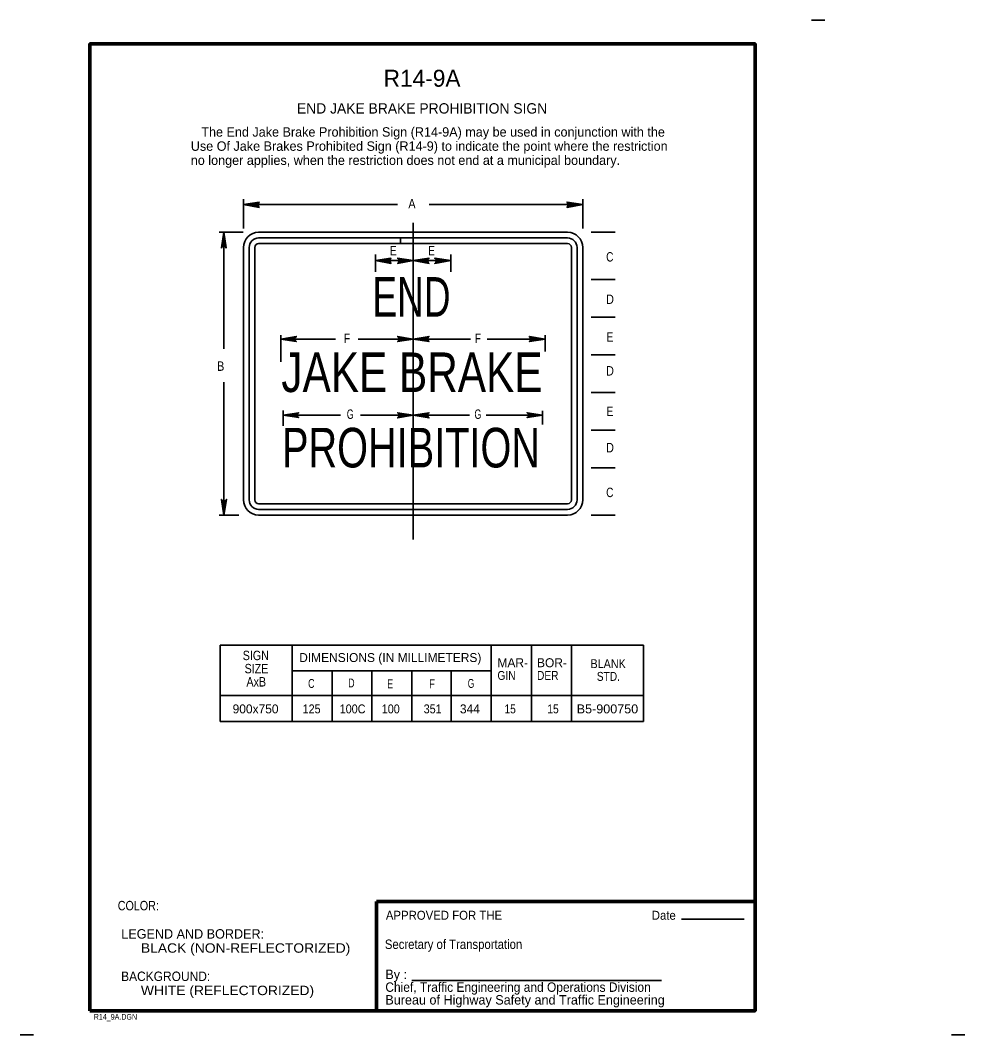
# Model space of a CAD drawing. Extents: x -0.29 to 0.3, y -0.007 to 0.262.
# Drawn here: x -0.2905 to -0.0399, y -0.0074 to 0.2617 of the extents above; entities that cross this region are included whole.
import ezdxf
from ezdxf.enums import TextEntityAlignment as Align

# ---------------------------------------------------------------- set-up
doc = ezdxf.new("R2010")
doc.units = 0
doc.header["$LTSCALE"] = 0.001
doc.linetypes.add('LONG_DASH_SHORT_DASH', pattern=[9.9, 6, -1.2, 1.5, -1.2])
for name, color, linetype, lineweight in [('1', 7, 'Continuous', 35), ('11', 7, 'Continuous', 35), ('12', 7, 'Continuous', 35), ('3', 7, 'Continuous', 35)]:
    doc.layers.add(name, color=color, linetype=linetype, lineweight=lineweight)
doc.layers.add('2', color=7, linetype='Continuous')

msp = doc.modelspace()

# ---------------------------------------------------------------- linework, layer by layer
at = {"layer": '1'}
for p, q in [((-0.077, 0.26175), (-0.0805, 0.26175)), ((-0.115, 0.02325), (-0.098375, 0.02325)), ((-0.186625, 0.007), (-0.120375, 0.007)), ((-0.287, -0.007375), (-0.2905, -0.007375))]:
    msp.add_line(p, q, dxfattribs=at)
at = {"layer": '1', "lineweight": 70}
for q in [(-0.0955, 0.028), (-0.196, -0.001)]:
    msp.add_line((-0.196, 0.028), q, dxfattribs=at)
msp.add_lwpolyline([(-0.272, -0.001), (-0.0955, -0.001), (-0.0955, 0.2555), (-0.272, 0.2555)], close=True, dxfattribs=at)
at = {"layer": '11'}
for p, q in [((-0.22725, 0.2055), (-0.14525, 0.2055)), ((-0.23125, 0.1345), (-0.23125, 0.2015)), ((-0.14125, 0.1345), (-0.14125, 0.2015)), ((-0.14525, 0.1305), (-0.22725, 0.1305))]:
    msp.add_line(p, q, dxfattribs=at)
for centre, start, end in [((-0.22725, 0.2015), 90, 180), ((-0.14525, 0.2015), 0, 90), ((-0.22725, 0.1345), 180, 270), ((-0.14525, 0.1345), 270, 0)]:
    msp.add_arc(centre, 0.004, start, end, dxfattribs=at)
at = {"layer": '12'}
msp.add_line((-0.039875, -0.007375), (-0.043375, -0.007375), dxfattribs=at)
at = {"layer": '3'}
for p, q in [((-0.23125, 0.2065), (-0.23125, 0.21425)), ((-0.190375, 0.212875), (-0.23125, 0.212875)), ((-0.14125, 0.212875), (-0.182, 0.212875)), ((-0.14125, 0.2065), (-0.14125, 0.21425)), ((-0.231375, 0.2055), (-0.23775, 0.2055)), ((-0.2365, 0.174625), (-0.2365, 0.2055)), ((-0.139, 0.2055), (-0.132625, 0.2055)), ((-0.14525, 0.2025), (-0.189625, 0.2025)), ((-0.22975, 0.1345), (-0.22975, 0.2015)), ((-0.22825, 0.2015), (-0.22825, 0.1345)), ((-0.19625, 0.199625), (-0.19625, 0.195)), ((-0.17625, 0.199625), (-0.17625, 0.195)), ((-0.14425, 0.1345), (-0.14425, 0.2015)), ((-0.14275, 0.2015), (-0.14275, 0.1345)), ((-0.18625, 0.198), (-0.19625, 0.198)), ((-0.18625, 0.198), (-0.17625, 0.198)), ((-0.139, 0.193), (-0.132625, 0.193)), ((-0.139, 0.183), (-0.132625, 0.183)), ((-0.221375, 0.171125), (-0.221375, 0.17825)), ((-0.15125, 0.173875), (-0.15125, 0.17825)), ((-0.206875, 0.177125), (-0.221375, 0.177125)), ((-0.18625, 0.177125), (-0.200875, 0.177125)), ((-0.18625, 0.177125), (-0.171, 0.177125)), ((-0.166625, 0.177125), (-0.15125, 0.177125)), ((-0.139, 0.173), (-0.132625, 0.173)), ((-0.23125, 0.168625), (-0.23125, 0.160375)), ((-0.14125, 0.167625), (-0.14125, 0.160375)), ((-0.2365, 0.1305), (-0.2365, 0.16575)), ((-0.139, 0.163), (-0.132625, 0.163)), ((-0.22075, 0.154125), (-0.22075, 0.15825)), ((-0.2055, 0.157), (-0.22075, 0.157)), ((-0.18625, 0.157), (-0.20025, 0.157)), ((-0.18625, 0.157), (-0.17125, 0.157)), ((-0.166875, 0.157), (-0.151875, 0.157)), ((-0.151875, 0.1545), (-0.151875, 0.158125)), ((-0.139, 0.153), (-0.132625, 0.153)), ((-0.139, 0.143), (-0.132625, 0.143)), ((-0.22725, 0.1335), (-0.14525, 0.1335)), ((-0.14525, 0.132), (-0.22725, 0.132)), ((-0.2325, 0.1305), (-0.23775, 0.1305)), ((-0.139, 0.1305), (-0.132625, 0.1305)), ((-0.2375, 0.096), (-0.125125, 0.096)), ((-0.2375, 0.096), (-0.2375, 0.07575)), ((-0.218375, 0.096), (-0.218375, 0.07575)), ((-0.1655, 0.096), (-0.1655, 0.07575)), ((-0.154875, 0.096), (-0.154875, 0.07575)), ((-0.14425, 0.096), (-0.14425, 0.07575)), ((-0.125125, 0.096), (-0.125125, 0.07575)), ((-0.1655, 0.089125), (-0.218375, 0.089125)), ((-0.20775, 0.089125), (-0.20775, 0.07575)), ((-0.19725, 0.089125), (-0.19725, 0.07575)), ((-0.186625, 0.089125), (-0.186625, 0.07575)), ((-0.176125, 0.089125), (-0.176125, 0.07575)), ((-0.2375, 0.082625), (-0.125125, 0.082625)), ((-0.2375, 0.07575), (-0.125125, 0.07575))]:
    msp.add_line(p, q, dxfattribs=at)
at = {"layer": '3', "linetype": 'LONG_DASH_SHORT_DASH'}
msp.add_line((-0.18625, 0.208), (-0.18625, 0.124), dxfattribs=at)
at = {"layer": '3'}
for points in [[(-0.22725, 0.21325), (-0.227375, 0.213), (-0.23125, 0.212875), (-0.22725, 0.21325), (-0.227125, 0.2135), (-0.23125, 0.212875), (-0.227375, 0.212625), (-0.22725, 0.212375), (-0.23125, 0.212875), (-0.227125, 0.212125), (-0.22725, 0.212375)], [(-0.14525, 0.212375), (-0.145125, 0.212625), (-0.14125, 0.212875), (-0.14525, 0.212375), (-0.145375, 0.212125), (-0.14125, 0.212875), (-0.145125, 0.213), (-0.14525, 0.21325), (-0.14125, 0.212875), (-0.145375, 0.2135), (-0.14525, 0.21325)], [(-0.237, 0.201625), (-0.23675, 0.20175), (-0.2365, 0.2055), (-0.237, 0.201625), (-0.237125, 0.201375), (-0.2365, 0.2055), (-0.23625, 0.20175), (-0.236, 0.201625), (-0.2365, 0.2055), (-0.235875, 0.201375), (-0.236, 0.201625)], [(-0.22725, 0.204), (-0.189625, 0.204), (-0.189625, 0.2025), (-0.22725, 0.2025)], [(-0.189625, 0.2025), (-0.189625, 0.204), (-0.14525, 0.204)], [(-0.19225, 0.1985), (-0.192375, 0.198125), (-0.19625, 0.198), (-0.19225, 0.1985), (-0.192125, 0.198625), (-0.19625, 0.198), (-0.192375, 0.19775), (-0.19225, 0.1975), (-0.19625, 0.198), (-0.192125, 0.19725), (-0.19225, 0.1975)], [(-0.190125, 0.1975), (-0.19, 0.19775), (-0.18625, 0.198), (-0.190125, 0.1975), (-0.190375, 0.19725), (-0.18625, 0.198), (-0.19, 0.198125), (-0.190125, 0.1985), (-0.18625, 0.198), (-0.190375, 0.198625), (-0.190125, 0.1985)], [(-0.18225, 0.1975), (-0.182375, 0.19775), (-0.18625, 0.198), (-0.18225, 0.1975), (-0.182, 0.19725), (-0.18625, 0.198), (-0.182375, 0.198125), (-0.18225, 0.1985), (-0.18625, 0.198), (-0.182, 0.198625), (-0.18225, 0.1985)], [(-0.18025, 0.1985), (-0.180125, 0.198125), (-0.17625, 0.198), (-0.18025, 0.1985), (-0.1805, 0.198625), (-0.17625, 0.198), (-0.180125, 0.19775), (-0.18025, 0.1975), (-0.17625, 0.198), (-0.1805, 0.19725), (-0.18025, 0.1975)], [(-0.2175, 0.177625), (-0.217625, 0.177375), (-0.221375, 0.177125), (-0.2175, 0.177625), (-0.21725, 0.177875), (-0.221375, 0.177125), (-0.217625, 0.177), (-0.2175, 0.17675), (-0.221375, 0.177125), (-0.21725, 0.1765), (-0.2175, 0.17675)], [(-0.190125, 0.176625), (-0.19, 0.177), (-0.18625, 0.177125), (-0.190125, 0.176625), (-0.190375, 0.1765), (-0.18625, 0.177125), (-0.19, 0.177375), (-0.190125, 0.177625), (-0.18625, 0.177125), (-0.190375, 0.177875), (-0.190125, 0.177625)], [(-0.18225, 0.177625), (-0.182375, 0.177375), (-0.18625, 0.177125), (-0.18225, 0.177625), (-0.182, 0.177875), (-0.18625, 0.177125), (-0.182375, 0.177), (-0.18225, 0.17675), (-0.18625, 0.177125), (-0.182, 0.1765), (-0.18225, 0.17675)], [(-0.15525, 0.176625), (-0.155, 0.177), (-0.15125, 0.177125), (-0.15525, 0.176625), (-0.155375, 0.1765), (-0.15125, 0.177125), (-0.155, 0.177375), (-0.15525, 0.177625), (-0.15125, 0.177125), (-0.155375, 0.177875), (-0.15525, 0.177625)], [(-0.216875, 0.1575), (-0.217, 0.15725), (-0.22075, 0.157), (-0.216875, 0.1575), (-0.216625, 0.157625), (-0.22075, 0.157), (-0.217, 0.15675), (-0.216875, 0.1565), (-0.22075, 0.157), (-0.216625, 0.156375), (-0.216875, 0.1565)], [(-0.190125, 0.1565), (-0.19, 0.15675), (-0.18625, 0.157), (-0.190125, 0.1565), (-0.190375, 0.15625), (-0.18625, 0.157), (-0.19, 0.157125), (-0.190125, 0.1575), (-0.18625, 0.157), (-0.190375, 0.157625), (-0.190125, 0.1575)], [(-0.18225, 0.1565), (-0.182375, 0.15675), (-0.18625, 0.157), (-0.18225, 0.1565), (-0.182, 0.15625), (-0.18625, 0.157), (-0.182375, 0.157125), (-0.18225, 0.1575), (-0.18625, 0.157), (-0.182, 0.157625), (-0.18225, 0.1575)], [(-0.15575, 0.1575), (-0.155625, 0.15725), (-0.151875, 0.157), (-0.15575, 0.1575), (-0.156, 0.157625), (-0.151875, 0.157), (-0.155625, 0.15675), (-0.15575, 0.1565), (-0.151875, 0.157), (-0.156, 0.156375), (-0.15575, 0.1565)], [(-0.236, 0.134375), (-0.23625, 0.13425), (-0.2365, 0.1305), (-0.236, 0.134375), (-0.23575, 0.134625), (-0.2365, 0.1305), (-0.236625, 0.13425), (-0.237, 0.134375), (-0.2365, 0.1305), (-0.237125, 0.134625), (-0.237, 0.134375)]]:
    msp.add_lwpolyline(points, dxfattribs=at)
for centre, radius, start, end in [((-0.22725, 0.2015), 0.0025, 90, 180), ((-0.22725, 0.2015), 0.001, 90, 180), ((-0.14525, 0.2015), 0.0025, 0, 90), ((-0.14525, 0.2015), 0.001, 0, 90), ((-0.22725, 0.1345), 0.0025, 180, 270), ((-0.22725, 0.1345), 0.001, 180, 270), ((-0.14525, 0.1345), 0.0025, 270, 0), ((-0.14525, 0.1345), 0.001, 270, 0)]:
    msp.add_arc(centre, radius, start, end, dxfattribs=at)

# ---------------------------------------------------------------- texts
at = {"layer": '1'}
for s, height, p in [('R14-9A', 0.0045, (-0.183875, 0.244125)), ('END JAKE BRAKE PROHIBITION SIGN', 0.00275, (-0.183875, 0.237))]:
    msp.add_text(s, height=height, dxfattribs=at).set_placement(p, align=Align.CENTER)
for s, height, width, p in [('COLOR:', 0.0025, 0.85, (-0.264625, 0.025625)), ('      BLACK (NON-REFLECTORIZED)', 0.0025, 1.1, (-0.264625, 0.014375)), ('Secretary of Transportation', 0.0025, 0.9, (-0.19375, 0.015375)), (' BACKGROUND:', 0.0025, 0.95, (-0.264625, 0.006875)), ('      WHITE (REFLECTORIZED)', 0.0025, 1.1, (-0.264625, 0.003125)), ('Chief, Traffic Engineering and Operations Division', 0.0025, 0.95, (-0.193625, 0.004)), ('R14_9A.DGN', 0.0015, 0.75, (-0.271, -0.003375))]:
    msp.add_text(s, height=height, dxfattribs=dict(at, width=width)).set_placement(p)
at = {"layer": '1', "width": 0.95}
for s, p in [('APPROVED FOR THE', (-0.178063, 0.023125)), ('Date ', (-0.119313, 0.023125))]:
    msp.add_text(s, height=0.002375, dxfattribs=at).set_placement(p, align=Align.CENTER)
at = {"layer": '1'}
for s, p in [(' LEGEND AND BORDER:', (-0.264625, 0.018125)), ('By :', (-0.193625, 0.007375)), ('Bureau of Highway Safety and Traffic Engineering', (-0.193625, 0.000625))]:
    msp.add_text(s, height=0.0025, dxfattribs=at).set_placement(p)
at = {"layer": '12'}
for s, height, width, p in [('END', 0.01049, 0.7, (-0.186688, 0.183125)), ('JAKE BRAKE', 0.0105, 0.8, (-0.186562, 0.163125)), ('PROHIBITION', 0.0105, 0.75, (-0.186812, 0.143125))]:
    msp.add_text(s, height=height, dxfattribs=dict(at, width=width)).set_placement(p, align=Align.CENTER)
at = {"layer": '2'}
for s, p in [('   The End Jake Brake Prohibition Sign (R14-9A) may be used in conjunction with the', (-0.24525, 0.230875)), ('Use Of Jake Brakes Prohibited Sign (R14-9) to indicate the point where the restriction', (-0.24525, 0.227125)), ('no longer applies, when the restriction does not end at a municipal boundary.', (-0.24525, 0.223375))]:
    msp.add_text(s, height=0.0025, dxfattribs=at).set_placement(p)
at = {"layer": '3'}
for s, height, width, p in [('A', 0.002501, 0.85, (-0.186562, 0.211875)), ('E', 0.0025, 0.8, (-0.1915, 0.199375)), ('E', 0.0025, 0.8, (-0.181375, 0.199375)), ('C', 0.002498, 0.8, (-0.134063, 0.19775)), ('D', 0.002498, 0.85, (-0.134, 0.1865)), ('F', 0.0025, 0.8, (-0.203813, 0.176125)), ('F', 0.0025, 0.8, (-0.169063, 0.176125)), ('E', 0.002498, 0.8, (-0.134, 0.1765)), ('B', 0.002501, 0.85, (-0.237313, 0.16875)), ('D', 0.002498, 0.85, (-0.134, 0.1675)), ('E', 0.002498, 0.8, (-0.134, 0.15675)), ('G', 0.0025, 0.7, (-0.202937, 0.156)), ('G', 0.0025, 0.7, (-0.169063, 0.156)), ('D', 0.002498, 0.85, (-0.134, 0.147125)), ('C', 0.002498, 0.8, (-0.134063, 0.13525)), ('SIGN', 0.0025, 0.85, (-0.228, 0.092)), ('BLANK', 0.002375, 0.9, (-0.1345, 0.089875)), ('SIZE', 0.0025, 0.85, (-0.227813, 0.0885)), ('STD.', 0.002375, 0.85, (-0.134438, 0.0865)), ('AxB', 0.0025, 0.85, (-0.227875, 0.085)), ('125', 0.002375, 0.9, (-0.213188, 0.077875)), ('100C', 0.002375, 0.9, (-0.202313, 0.077875)), ('100', 0.002375, 0.9, (-0.192188, 0.077875)), ('351', 0.002375, 0.9, (-0.181063, 0.077875)), ('15', 0.002375, 0.85, (-0.1605, 0.077875)), ('15', 0.002375, 0.85, (-0.149125, 0.077875)), ('B5-900750', 0.002375, 1.05, (-0.134688, 0.077875))]:
    msp.add_text(s, height=height, dxfattribs=dict(at, width=width)).set_placement(p, align=Align.CENTER)
for s, p in [('DIMENSIONS (IN MILLIMETERS)', (-0.192312, 0.0915)), ('900x750', (-0.228063, 0.077875)), ('344', (-0.171187, 0.077875))]:
    msp.add_text(s, height=0.002375, dxfattribs=at).set_placement(p, align=Align.CENTER)
for s, p in [('MAR-', (-0.163875, 0.090125)), ('BOR-', (-0.153375, 0.090125))]:
    msp.add_text(s, height=0.002375, dxfattribs=at).set_placement(p)
for s, width, p in [('GIN', 0.85, (-0.163875, 0.08675)), ('DER', 0.85, (-0.153375, 0.08675)), ('C', 0.75, (-0.214125, 0.084625)), ('D', 0.75, (-0.2035, 0.08475)), ('E', 0.75, (-0.193125, 0.0845)), ('F', 0.8, (-0.182, 0.0845)), ('G', 0.7, (-0.17175, 0.084625))]:
    msp.add_text(s, height=0.002375, dxfattribs=dict(at, width=width)).set_placement(p)

doc.saveas('drawing.dxf')
